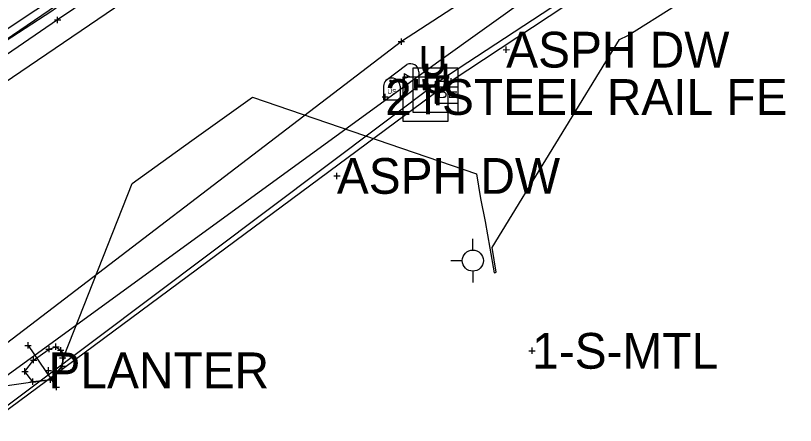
# Model space of a CAD drawing. Extents: x -1 to 1157254, y -1 to 2021979.
# Drawn here: x 1150523.9 to 1150680.9, y 2019736.2 to 2019818.7 of the extents above; entities that cross this region are included whole.
import ezdxf

# ---------------------------------------------------------------- set-up
doc = ezdxf.new("R2010")
doc.units = 0
for name, color, linetype in [('S_BUILDING_ANNOT', 7, 'Continuous'), ('S_CAL_CORNER_ANNOT', 7, 'Continuous'), ('S_CATCH_BASIN', 7, 'Continuous'), ('S_CATCH_BASIN_ANNOT', 7, 'Continuous'), ('S_CONTOUR_ANNOT', 7, 'Continuous'), ('S_CONTOUR_MAJOR', 7, 'Continuous'), ('S_CROSS_DRAIN', 7, 'Continuous'), ('S_CROSS_DRAIN_ANNOT', 7, 'Continuous'), ('S_DRIVEWAY_ANNOT', 7, 'Continuous'), ('S_DROP_INLET', 7, 'Continuous'), ('S_DTM_PAVEMENT', 7, 'Continuous'), ('S_EDGE_BITUMINOUS', 7, 'Continuous'), ('S_FENCE', 7, 'Continuous'), ('S_GAS_PUMP_ISLAND_ANNOT', 7, 'Continuous'), ('S_GATE', 7, 'Continuous')]:
    doc.layers.add(name, color=color, linetype=linetype)

msp = doc.modelspace()

# ---------------------------------------------------------------- linework, layer by layer
at = {"layer": 'S_BUILDING_ANNOT'}
for p, q in [((1150532.33, 2019817.2), (1150532.32, 2019818.47)), ((1150531.69, 2019817.84), (1150532.96, 2019817.84)), ((1150532.32, 2019817.84), (1150532.32, 2019817.84)), ((1150601.54, 2019812.83), (1150601.54, 2019814.1)), ((1150600.9, 2019813.46), (1150602.18, 2019813.47)), ((1150601.54, 2019813.47), (1150601.54, 2019813.47)), ((1150622.63, 2019811.21), (1150622.63, 2019812.48)), ((1150622, 2019811.84), (1150623.27, 2019811.85)), ((1150622.63, 2019811.84), (1150622.63, 2019811.84)), ((1150611.54, 2019804.83), (1150611.53, 2019806.1)), ((1150610.9, 2019805.47), (1150612.17, 2019805.47)), ((1150611.54, 2019805.47), (1150611.54, 2019805.47)), ((1150598.26, 2019801.67), (1150598.26, 2019802.94)), ((1150597.63, 2019802.31), (1150598.9, 2019802.31)), ((1150598.26, 2019802.31), (1150598.26, 2019802.31)), ((1150588.54, 2019785.79), (1150588.54, 2019787.06)), ((1150587.9, 2019786.42), (1150589.18, 2019786.42)), ((1150588.54, 2019786.42), (1150588.54, 2019786.42)), ((1150525.74, 2019752.3), (1150527.01, 2019752.3)), ((1150526.38, 2019751.66), (1150526.38, 2019752.94)), ((1150526.38, 2019752.3), (1150526.38, 2019752.3)), ((1150531.99, 2019751.39), (1150531.98, 2019752.66)), ((1150529.98, 2019751.53), (1150531.25, 2019751.53)), ((1150530.62, 2019750.9), (1150530.61, 2019752.17)), ((1150530.62, 2019751.53), (1150530.62, 2019751.53)), ((1150531.35, 2019752.02), (1150532.62, 2019752.03)), ((1150531.99, 2019752.02), (1150531.99, 2019752.02)), ((1150532.31, 2019751.34), (1150533.58, 2019751.34)), ((1150532.94, 2019750.7), (1150532.94, 2019751.97)), ((1150532.94, 2019751.34), (1150532.94, 2019751.34)), ((1150533.67, 2019749.53), (1150533.66, 2019750.8)), ((1150627.22, 2019751.2), (1150628.49, 2019751.2)), ((1150627.86, 2019750.57), (1150627.86, 2019751.84)), ((1150627.86, 2019751.2), (1150627.86, 2019751.2)), ((1150526.84, 2019749.32), (1150528.11, 2019749.32)), ((1150527.48, 2019748.69), (1150527.47, 2019749.96)), ((1150527.48, 2019749.32), (1150527.48, 2019749.32)), ((1150532.71, 2019749.78), (1150533.98, 2019749.78)), ((1150533.03, 2019750.16), (1150534.3, 2019750.16)), ((1150533.35, 2019749.14), (1150533.34, 2019750.41)), ((1150533.34, 2019749.78), (1150533.34, 2019749.78)), ((1150533.67, 2019750.16), (1150533.67, 2019750.16)), ((1150525.73, 2019746.41), (1150525.73, 2019747.68)), ((1150530.49, 2019746.63), (1150530.49, 2019747.91)), ((1150532.63, 2019748.11), (1150533.9, 2019748.12)), ((1150533.27, 2019747.48), (1150533.26, 2019748.75)), ((1150533.26, 2019748.12), (1150533.26, 2019748.12)), ((1150525.09, 2019747.04), (1150526.36, 2019747.04)), ((1150525.73, 2019747.04), (1150525.73, 2019747.04)), ((1150529.85, 2019747.27), (1150531.12, 2019747.27)), ((1150530.49, 2019747.27), (1150530.49, 2019747.27)), ((1150530.87, 2019744.76), (1150530.87, 2019746.03)), ((1150526.72, 2019744.97), (1150528, 2019744.97)), ((1150527.36, 2019744.33), (1150527.36, 2019745.6)), ((1150527.36, 2019744.97), (1150527.36, 2019744.97)), ((1150530.23, 2019745.39), (1150531.51, 2019745.39)), ((1150530.87, 2019745.39), (1150530.87, 2019745.39)), ((1150532.09, 2019743.26), (1150532.09, 2019744.54)), ((1150531.45, 2019743.9), (1150532.73, 2019743.9)), ((1150532.09, 2019743.9), (1150532.09, 2019743.9))]:
    msp.add_line(p, q, dxfattribs=at)
at = {"layer": 'S_CAL_CORNER_ANNOT'}
for points in [[(1150827.62, 2020008.19), (1150733.09, 2019947.48), (1150628.16, 2019877.65), (1150500.75, 2019790.99), (1150424.78, 2019737.67), (1150355.4, 2019749.66)], [(1150682.05, 2019865.85), (1150601.54, 2019813.47), (1150510.58, 2019743.97), (1150405.28, 2019665.92), (1150310.69, 2019593.56), (1150188.92, 2019499.64), (1150039.45, 2019388.15), (1149962.15, 2019331.17), (1149944.63, 2019319.08), (1149774.15, 2019191.52), (1149712.73, 2019145.6), (1149665.81, 2019108.74), (1149605.46, 2019057.66), (1149527.46, 2018983.58), (1149450.12, 2018902.93), (1149278.32, 2018738.82), (1149257.2, 2018716.38), (1149237.23, 2018691.25), (1149165.09, 2018617.77), (1149125.26, 2018579.57), (1149069.5, 2018523.84), (1149012.03, 2018473.77), (1148938.88, 2018408.55)]]:
    msp.add_lwpolyline(points, dxfattribs=at)
at = {"layer": 'S_CATCH_BASIN'}
for p, q in [((1150615.91, 2019771.48), (1150615.91, 2019773.72)), ((1150613.81, 2019769.35), (1150611.49, 2019769.35)), ((1150615.98, 2019764.93), (1150615.98, 2019767.26))]:
    msp.add_line(p, q, dxfattribs=at)
msp.add_circle((1150615.91, 2019769.37), 2.13, dxfattribs=at)
at = {"layer": 'S_CATCH_BASIN_ANNOT'}
for points in [[(1150603.87, 2019799.16), (1150603.87, 2019808.16), (1150612.87, 2019808.16), (1150612.87, 2019799.16)], [(1150601.88, 2019797.35), (1150601.88, 2019806.35), (1150610.87, 2019806.35), (1150610.87, 2019797.35)]]:
    msp.add_lwpolyline(points, close=True, dxfattribs=at)
at = {"layer": 'S_CONTOUR_ANNOT'}
msp.add_lwpolyline([(1150857.08, 2020031.73), (1150832.22, 2020016.43), (1150747.37, 2019963.08), (1150692.94, 2019929.63), (1150639.49, 2019893), (1150583.9, 2019856.96), (1150484.25, 2019790.85), (1150433.08, 2019750.74), (1150355.8, 2019695.65), (1150341.28, 2019681.73), (1150287.94, 2019641.18), (1150216.41, 2019587.25), (1150034.4, 2019445.88), (1149979.98, 2019405.6), (1149934.92, 2019374.11), (1149784.56, 2019258.12)], dxfattribs=at)
at = {"layer": 'S_CROSS_DRAIN'}
for p, q in [((1150598.49, 2019805.73), (1150602.62, 2019808.84)), ((1150605.05, 2019807.36), (1150605.05, 2019804.65)), ((1150602.1, 2019807.02), (1150602.1, 2019804.3)), ((1150597.93, 2019804.46), (1150597.93, 2019801.74)), ((1150601.26, 2019801.74), (1150605.05, 2019804.65)), ((1150601.26, 2019804.46), (1150601.26, 2019801.74)), ((1150597.93, 2019801.74), (1150601.26, 2019801.74))]:
    msp.add_line(p, q, dxfattribs=at)
for points in [[(1150602.1, 2019807.02), (1150603.21, 2019806.35), (1150602.1, 2019806.01)], [(1150599.12, 2019805.57), (1150599.34, 2019805.43), (1150599.34, 2019805.04), (1150599.64, 2019805.04), (1150599.64, 2019805.4), (1150599.45, 2019805.65), (1150599.12, 2019805.6)]]:
    msp.add_lwpolyline(points, dxfattribs=at)
for centre, end in [((1150603.39, 2019807.36), 117.5718), ((1150599.6, 2019804.46), 180)]:
    msp.add_arc(centre, 1.66, 0, end, dxfattribs=at)
msp.add_ellipse((1150602.1, 2019804.3), major_axis=(0.145, 0.132), ratio=0.564646, dxfattribs=at)
at = {"layer": 'S_CROSS_DRAIN_ANNOT'}
msp.add_lwpolyline([(1150608.39, 2019801.03), (1150608.39, 2019805.53), (1150612.89, 2019805.53), (1150612.89, 2019801.03)], close=True, dxfattribs=at)
at = {"layer": 'S_DRIVEWAY_ANNOT'}
for points in [[(1150598.96, 2019864.81), (1150597.2, 2019863.93), (1150584.79, 2019854.84), (1150547.42, 2019831.48), (1150531.17, 2019819.56), (1150484.14, 2019789.03), (1150452.15, 2019766.06), (1150432.57, 2019756.16), (1150424.45, 2019750.95), (1150423.85, 2019749.62)], [(1150599.27, 2019863.57), (1150597.85, 2019862.02), (1150585.83, 2019852.79), (1150548.91, 2019829.11), (1150532.32, 2019817.84), (1150486.45, 2019786.45), (1150452.29, 2019764.02), (1150433.91, 2019753.35), (1150425.82, 2019748.97), (1150424.36, 2019748.74)]]:
    msp.add_lwpolyline(points, dxfattribs=at)
at = {"layer": 'S_DROP_INLET'}
for points in [[(1150831.49, 2020022.11), (1150729.58, 2019954.73), (1150690.81, 2019927.93), (1150657.92, 2019906.59), (1150452.8, 2019766.7), (1150415.16, 2019745.86)], [(1150852.18, 2019973.05), (1150778.54, 2019928.45), (1150770.16, 2019919.18), (1150703.8, 2019877.29), (1150608.63, 2019809.12), (1150513.43, 2019739.89), (1150405.92, 2019663.65), (1150352.2, 2019622.72), (1150343.81, 2019614.74), (1150336.72, 2019606.98), (1150314.89, 2019591.84), (1150193.25, 2019498.28), (1150112.69, 2019435.49), (1150059.59, 2019406.16), (1150037.88, 2019389.79), (1149962.99, 2019329.91), (1149914.05, 2019297.4), (1149863.26, 2019256.98)], [(1150853.56, 2019969.99), (1150781.71, 2019924.44), (1150774.41, 2019914.43), (1150697.13, 2019863.12), (1150609.24, 2019805.57), (1150516.58, 2019735.98), (1150408.74, 2019655.56), (1150359.48, 2019622.09), (1150352.77, 2019615.32), (1150355.2, 2019603.6), (1150359.35, 2019593.87)]]:
    msp.add_lwpolyline(points, dxfattribs=at)
at = {"layer": 'S_DTM_PAVEMENT'}
msp.add_lwpolyline([(1150526.38, 2019752.3), (1150532.09, 2019743.9)], dxfattribs=at)
at = {"layer": 'S_EDGE_BITUMINOUS'}
msp.add_lwpolyline([(1150533.34, 2019749.78), (1150533.26, 2019748.12), (1150530.87, 2019745.39), (1150527.36, 2019744.97), (1150525.73, 2019747.04), (1150527.48, 2019749.32), (1150530.62, 2019751.53), (1150531.99, 2019752.02), (1150532.94, 2019751.34), (1150533.67, 2019750.16)], dxfattribs=at)
at = {"layer": 'S_FENCE'}
msp.add_lwpolyline([(1150775.16, 2019913.88), (1150697.15, 2019862.05), (1150611.54, 2019805.47), (1150516.86, 2019735.37), (1150402.98, 2019659.79), (1150352.98, 2019622.15), (1150350.25, 2019606.72), (1150331.34, 2019598.55), (1150196.24, 2019490.87), (1150043.62, 2019380.11), (1149966.77, 2019324.72), (1149934.21, 2019308.48), (1149916.33, 2019289.12), (1149866.68, 2019250.91)], dxfattribs=at)
at = {"layer": 'S_GAS_PUMP_ISLAND_ANNOT'}
msp.add_lwpolyline([(1150475.18, 2019729.75), (1150486.94, 2019739.18), (1150527.36, 2019744.97), (1150530.87, 2019745.39), (1150533.26, 2019748.12), (1150533.67, 2019750.16), (1150547.31, 2019784.88), (1150559.34, 2019793.54), (1150571.53, 2019802.29), (1150616.62, 2019786.84), (1150617.46, 2019781.87), (1150618.41, 2019777.23), (1150619.34, 2019771.87), (1150620.18, 2019766.9), (1150620.46, 2019766.99), (1150620.64, 2019767.04), (1150619.8, 2019772.01), (1150645.46, 2019813.87), (1150647.12, 2019814.66), (1150656.68, 2019820.74), (1150672.01, 2019831.09), (1150695.8, 2019846.94)], dxfattribs=at)

# ---------------------------------------------------------------- texts
at = {"layer": 'S_CATCH_BASIN_ANNOT'}
for p in [(1150606.44, 2019800.66), (1150604.44, 2019798.85)]:
    msp.add_text('T', height=6, dxfattribs=at).set_placement(p)
at = {"layer": 'S_CONTOUR_MAJOR'}
for p in [(1150605, 2019806.57), (1150605.61, 2019803.02)]:
    msp.add_text('U', height=6, dxfattribs=at).set_placement(p)
at = {"layer": 'S_CROSS_DRAIN'}
msp.add_text('US', height=0.96, dxfattribs=at).set_placement((1150598.7, 2019802.94))
at = {"layer": 'S_CROSS_DRAIN_ANNOT'}
msp.add_text('BE', height=2.399, dxfattribs=at).set_placement((1150608.71, 2019802.08))
at = {"layer": 'S_GATE'}
for s, p in [('ASPH DW', (1150622.63, 2019808.24)), ('2" STEEL RAIL FE', (1150598.26, 2019798.71)), ('ASPH DW', (1150588.54, 2019782.82)), ('1-S-MTL', (1150627.86, 2019747.6)), ('PLANTER', (1150530.49, 2019743.67))]:
    msp.add_text(s, height=7.2, dxfattribs=at).set_placement(p)

doc.saveas('drawing.dxf')
